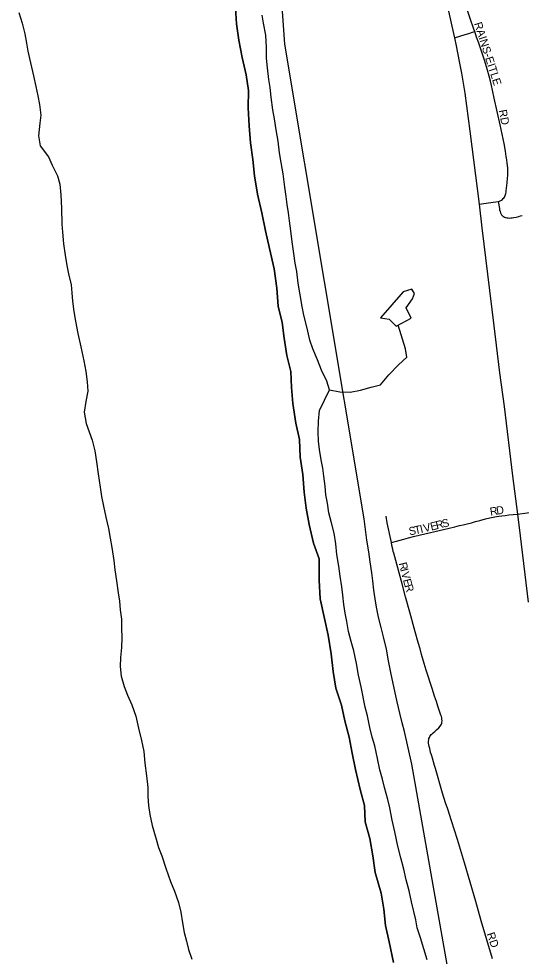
# Model space of a CAD drawing. Extents: x 1451455 to 1749751, y 218250 to 574981.
# Drawn here: x 1601926 to 1605068, y 245182 to 251036 of the extents above; entities that cross this region are included whole.
import ezdxf

# ---------------------------------------------------------------- set-up
doc = ezdxf.new("R2010")
doc.units = 0
for name, color, linetype in [('GM_X_City_Street', 7, 'Continuous'), ('GM_X_City_Street_Text', 7, 'Continuous'), ('GM_X_Corporation', 7, 'Continuous'), ('GM_X_County', 7, 'Continuous'), ('GM_X_Major_River', 7, 'Continuous'), ('GM_X_Minor_Lake', 7, 'Continuous'), ('GM_X_Minor_River', 7, 'Continuous'), ('GM_X_Township', 7, 'Continuous'), ('GM_X_US_Route', 7, 'Continuous')]:
    doc.layers.add(name, color=color, linetype=linetype)

msp = doc.modelspace()

# ---------------------------------------------------------------- linework, layer by layer
at = {"layer": 'GM_X_City_Street'}
for points in [[(1604776.7, 250957), (1604772.1, 250970.4), (1604749.1, 251038.3), (1604679.3, 251250.5), (1604645, 251349.6), (1604639.5, 251368.5), (1604636, 251382.3), (1604634.7, 251392.7), (1604634.3, 251401.8), (1604634.7, 251409.5), (1604635.5, 251416), (1604637.3, 251422.1)], [(1604650, 250917.2), (1604683.3, 250927), (1604717.2, 250937), (1604739.6, 250944.2), (1604762.7, 250952.2), (1604776.7, 250957)], [(1604923.9, 249895.9), (1604932.3, 249898.1), (1604939.2, 249900.7), (1604945.3, 249904.2), (1604950.9, 249908.5), (1604955.7, 249913.3), (1604959.2, 249916.8), (1604963.1, 249922.4), (1604965.7, 249926.7), (1604967.9, 249932.8), (1604969.4, 249938), (1604970.9, 249944.1), (1604972.7, 249952.4), (1604973.9, 249961.9), (1604978.8, 250011.1), (1604982.2, 250041.3), (1604983.3, 250056.8), (1604983.9, 250070.8), (1604983.9, 250079.9), (1604983.9, 250092.5), (1604983, 250105.1), (1604981.9, 250119), (1604980, 250135.1), (1604977.3, 250154.7), (1604974.3, 250175.8), (1604968.3, 250210.2), (1604960, 250257), (1604935.3, 250374.2), (1604917.1, 250457.1), (1604899.3, 250540.2), (1604888, 250591.2), (1604881.5, 250619.4), (1604875, 250647.2), (1604867.2, 250678.5), (1604857.2, 250714.9), (1604848.9, 250743.1), (1604840.7, 250770.9), (1604830.6, 250803.3), (1604819.9, 250834.3), (1604802.9, 250882.9), (1604789, 250922), (1604776.7, 250957)], [(1604803.8, 249878.4), (1604847.9, 249884.6), (1604891.4, 249890.7), (1604908.8, 249893.3), (1604923.9, 249895.9)], [(1604923.9, 249895.9), (1604930.9, 249851.2), (1604932.6, 249843), (1604935, 249831.8), (1604938.2, 249823.5), (1604941.7, 249816.5), (1604945.3, 249811.5), (1604949.1, 249806.9), (1604952.9, 249803.5), (1604957.7, 249800.5), (1604963.8, 249797.4), (1604970.3, 249794.8), (1604977.7, 249793.1), (1604985.6, 249792.3), (1604993.3, 249791.8), (1605002.1, 249792.1), (1605011.1, 249793.1), (1605021.7, 249794.5), (1605036.7, 249797.8), (1605053.6, 249802.2), (1605063.6, 249804.8), (1605073.6, 249808.3)], [(1605043.4, 247942.8), (1605103.7, 247950.2), (1605208.8, 247963.4)], [(1604255.8, 247765.2), (1604230.4, 247889), (1604223, 247929.2)], [(1604255.8, 247765.2), (1604286.8, 247773.6), (1604334.5, 247786.6), (1604363.6, 247794.4), (1604393.5, 247802.2), (1604437.4, 247813.3), (1604580.6, 247847.4), (1604617, 247856.1), (1604652.6, 247864.3), (1604682.1, 247870.8), (1604705, 247876.1), (1604730.3, 247882.5), (1604755.7, 247889.2), (1604781.5, 247896), (1604808.4, 247903.3), (1604844, 247912.5), (1604870.5, 247919), (1604891.7, 247923.9), (1604912.2, 247927.7), (1604927.4, 247930.2), (1604946.7, 247932.9), (1604966.6, 247935.1), (1604989.2, 247937.3), (1605043.4, 247942.8)], [(1604889, 245164.7), (1604817.3, 245403.4), (1604783.8, 245523.4), (1604712.8, 245765.8), (1604668.6, 245910.1), (1604631.9, 246027.5), (1604607.7, 246100.6), (1604595, 246140.7), (1604576.4, 246200.8), (1604531.6, 246354.3), (1604525.6, 246373.8), (1604519.1, 246395.9), (1604512.1, 246418.1), (1604506, 246438.5), (1604501.3, 246453.7), (1604497.3, 246468.9), (1604495.2, 246479.3), (1604492.1, 246492.3), (1604490, 246502.3), (1604488.7, 246512.3), (1604488.2, 246519.8), (1604488.2, 246525.8), (1604489.1, 246532.9), (1604490.8, 246540.5), (1604493.4, 246547.9), (1604496.8, 246554.2), (1604500.4, 246560.5), (1604505.2, 246566.1), (1604510.4, 246571.3), (1604517.8, 246577.8), (1604527.7, 246586.1), (1604538.9, 246595.3), (1604553.5, 246608.6), (1604561.7, 246618.7), (1604565.5, 246624.7), (1604568.1, 246630.1), (1604570.2, 246636), (1604571.8, 246642.6), (1604572.6, 246652.4), (1604571.6, 246662), (1604570.2, 246670.3), (1604568.4, 246678.2), (1604565.5, 246687.6), (1604559.4, 246706.3), (1604547.2, 246743.8), (1604537.3, 246772.7), (1604526.1, 246805.9), (1604510.8, 246853.4), (1604473.8, 246968.2), (1604461.8, 247009.3), (1604444.8, 247065.7), (1604434.8, 247100.8), (1604424, 247141.6), (1604405.2, 247207.8), (1604371.7, 247331.2), (1604344.9, 247425.9), (1604322.2, 247508.1), (1604270.9, 247698.1), (1604267.8, 247710.2), (1604264.3, 247724.5), (1604259.5, 247746.2), (1604255.8, 247765.2)]]:
    msp.add_lwpolyline(points, dxfattribs=at)
at = {"layer": 'GM_X_Corporation'}
msp.add_lwpolyline([(1604616.6, 245058.8), (1604383.4, 246381.5), (1604338.8, 246584.5), (1604323.4, 246638.8), (1604308.1, 246699.1), (1604292.9, 246771.4), (1604279.4, 246825.7), (1604252.8, 246954.3), (1604237.6, 247026.7), (1604224.4, 247099), (1604207.3, 247177.4), (1604191.9, 247235.7), (1604174.6, 247300), (1604163.3, 247362.3), (1604153.9, 247414.5), (1604146.4, 247468.7), (1604139.1, 247526.9), (1604133.6, 247577.1), (1604122.4, 247645.4), (1604115, 247707.6), (1604101.8, 247779.9), (1604094.6, 247846.1), (1604085, 247913.6), (1603589, 250877.2), (1603525.6, 251789.6)], dxfattribs=at)
at = {"layer": 'GM_X_County'}
msp.add_lwpolyline([(1603280.6, 251104.7), (1603286.5, 251005), (1603302.7, 250901.6), (1603322.8, 250794.6), (1603348.6, 250686.9), (1603362.2, 250589.3), (1603360.2, 250480), (1603366.2, 250366.8), (1603374.3, 250261.7), (1603390.3, 250157.3), (1603400.2, 250055.1), (1603418.4, 249941.5), (1603446.4, 249825), (1603468.4, 249711), (1603493.2, 249600.8), (1603522.2, 249475), (1603539.9, 249354.3), (1603547.9, 249241.3), (1603572, 249140.4), (1603585.9, 249041.1), (1603602, 248933.8), (1603627.7, 248832.7), (1603631.6, 248734.2), (1603639.7, 248633), (1603657.9, 248511.3), (1603681.6, 248408.3), (1603685.5, 248298.8), (1603701.6, 248190.1), (1603711.5, 248080.2), (1603723.6, 247979.2), (1603741.8, 247878), (1603768.1, 247762.1), (1603803.4, 247663.9), (1603805.3, 247530.6), (1603811.4, 247414.5), (1603837.7, 247290.7), (1603859.6, 247187), (1603879.4, 247069.7), (1603891.4, 246959.6), (1603907.7, 246855.2), (1603943.9, 246750.5), (1603965.7, 246651.1), (1603991.6, 246549.1), (1604011.5, 246449.4), (1604031.5, 246347), (1604059.6, 246224), (1604087.1, 246123.6), (1604091.2, 246021.2), (1604121.5, 245917.9), (1604139.2, 245809), (1604155.4, 245703.7), (1604191.4, 245575.2), (1604209.1, 245474.7), (1604219.2, 245374.2), (1604241.4, 245270.8), (1604269.6, 245143.6)], dxfattribs=at)
at = {"layer": 'GM_X_Major_River'}
for points in [[(1601925.9, 251076.2), (1601947.1, 251009.8), (1601964.4, 250941.5), (1601973.7, 250883.3), (1601983.2, 250833.1), (1602000.4, 250760.7), (1602017.5, 250680.4), (1602032.7, 250614.1), (1602046.1, 250555.8), (1602055.5, 250501.6), (1602064.7, 250433.3), (1602058.1, 250383.3), (1602049.3, 250305.2), (1602060.6, 250243), (1602111.8, 250174.2), (1602135.3, 250121.9), (1602168.5, 250055.4), (1602181.9, 250003.1), (1602189.2, 249936.9), (1602192.3, 249850.7), (1602195.2, 249754.4), (1602198.6, 249704.3), (1602205.8, 249630), (1602217, 249559.8), (1602226.3, 249495.5), (1602237.7, 249443.3), (1602253, 249375), (1602258.4, 249324.8), (1602261.8, 249272.6), (1602271.1, 249208.4), (1602280.5, 249148.2), (1602295.6, 249069.8), (1602314.7, 248987.4), (1602333.7, 248901), (1602345, 248832.8), (1602354.3, 248768.5), (1602357.6, 248710.4), (1602344.9, 248646.4), (1602334.2, 248580.3), (1602347.4, 248508), (1602366.8, 248455.7), (1602384.3, 248405.4), (1602401.6, 248339), (1602412.8, 248268.8), (1602422, 248194.5), (1602435.1, 248110.1), (1602444.4, 248051.9), (1602455.8, 247991.6), (1602471, 247923.3), (1602486.2, 247853), (1602497.6, 247792.7), (1602508.9, 247734.5), (1602520, 247652.2), (1602527.4, 247593.9), (1602536.7, 247525.7), (1602547.8, 247451.4), (1602555.3, 247399.2), (1602560.7, 247345), (1602568, 247286.8), (1602569.4, 247230.6), (1602570.8, 247170.5), (1602568.1, 247110.4), (1602561.4, 247048.3), (1602560.8, 246990.2), (1602566.1, 246930), (1602585.4, 246865.6), (1602606.9, 246811.2), (1602632.2, 246750.8), (1602657.4, 246680.4), (1602674.6, 246606), (1602693.8, 246529.6), (1602707.1, 246461.3), (1602714.3, 246387), (1602725.4, 246308.7), (1602732.6, 246236.5), (1602734, 246180.3), (1602737.4, 246122.2), (1602744.8, 246067.9), (1602760, 245997.6), (1602785.1, 245913.1), (1602800.6, 245860.8), (1602820, 245808.5), (1602845.2, 245732), (1602874.3, 245647.5), (1602899.6, 245587.1), (1602924.8, 245516.6), (1602940.2, 245456.3), (1602949.5, 245390), (1602960.8, 245329.8), (1602974.2, 245275.5), (1602987.7, 245223.2), (1603009, 245162.8)], [(1603627.2, 249712.2), (1603617.9, 249774.5), (1603612.4, 249824.6), (1603605, 249876.8), (1603597.5, 249927), (1603590.2, 249985.2), (1603579.1, 250067.5), (1603565.9, 250137.8), (1603556.6, 250200), (1603547.4, 250272.3), (1603536.2, 250342.6), (1603524.9, 250410.8), (1603515.6, 250467), (1603504.5, 250547.3), (1603497.1, 250607.5), (1603489.7, 250657.7), (1603480.5, 250730), (1603475.2, 250790.2), (1603475.9, 250856.3), (1603470.8, 250934.5), (1603455.6, 251008.8), (1603448.2, 251059)], [(1604479.5, 245158.3), (1604458.2, 245228.7), (1604436.9, 245297.1), (1604417.6, 245359.5), (1604408.2, 245409.7), (1604381.4, 245522.3), (1604366.1, 245590.6), (1604348.8, 245659), (1604333.6, 245725.3), (1604314.3, 245795.7), (1604295.1, 245870.1), (1604278.1, 245958.5), (1604260.9, 246030.9), (1604245.7, 246109.2), (1604234.3, 246161.5), (1604213.1, 246235.9), (1604199.6, 246288.1), (1604184.3, 246346.5), (1604169, 246416.8), (1604151.9, 246495.2), (1604136.5, 246549.5), (1604121.1, 246609.8), (1604105.9, 246682.1), (1604092.5, 246736.4), (1604065.9, 246865), (1604050.7, 246937.3), (1604037.5, 247009.6), (1604020.3, 247088), (1604004.9, 247146.3), (1603987.6, 247210.7), (1603976.3, 247272.9), (1603966.9, 247325.2), (1603959.5, 247379.4), (1603952.1, 247437.6), (1603946.7, 247487.8), (1603935.4, 247556), (1603928.1, 247618.3), (1603914.9, 247690.6), (1603907.6, 247756.8), (1603898.3, 247823.1), (1603881.1, 247889.4), (1603865.7, 247951.7), (1603856.4, 248012), (1603846.9, 248062.2), (1603841.5, 248116.4), (1603834.2, 248180.6), (1603826.8, 248230.8), (1603817.4, 248281), (1603806.1, 248345.3), (1603800.7, 248399.4), (1603797.3, 248457.6), (1603800, 248523.7), (1603806.8, 248589.8), (1603837.5, 248653.6), (1603868.2, 248719.4), (1603852.8, 248773.7), (1603819.6, 248842.2), (1603794.3, 248906.6), (1603765, 248975.1), (1603745.6, 249029.4), (1603728.4, 249103.8), (1603709.3, 249186.2), (1603697.9, 249238.4), (1603684.7, 249312.7), (1603673.5, 249385), (1603664.3, 249457.3), (1603654.9, 249509.5), (1603645.6, 249569.7), (1603636.4, 249644), (1603627.2, 249712.2)]]:
    msp.add_lwpolyline(points, dxfattribs=at)
at = {"layer": 'GM_X_Minor_Lake'}
for points in [[(1604379.5, 249166.2), (1604348.4, 249230.8), (1604387.2, 249286.4), (1604399.8, 249320.3), (1604384.1, 249346.6), (1604329.9, 249331.4), (1604187.3, 249169), (1604241.2, 249160.2), (1604286.6, 249117.4)], [(1604286.6, 249117.4), (1604379.5, 249166.2)]]:
    msp.add_lwpolyline(points, dxfattribs=at)
at = {"layer": 'GM_X_Minor_River'}
msp.add_lwpolyline([(1603868.2, 248719.4), (1603934.2, 248707.5), (1603998.2, 248704.5), (1604062.5, 248717.7), (1604128.8, 248734.8), (1604187.1, 248749.9), (1604240.1, 248813.4), (1604301, 248874.6), (1604351.8, 248922), (1604344.6, 248974.2), (1604298.2, 249123.5)], dxfattribs=at)
at = {"layer": 'GM_X_Township'}
msp.add_lwpolyline([(1604269.6, 245143.6), (1604241.4, 245270.8), (1604219.2, 245374.2), (1604209.1, 245474.7), (1604191.4, 245575.2), (1604155.4, 245703.7), (1604139.2, 245809), (1604121.5, 245917.9), (1604091.2, 246021.2), (1604087.1, 246123.6), (1604059.6, 246224), (1604031.5, 246347), (1604011.5, 246449.4), (1603991.6, 246549.1), (1603965.7, 246651.1), (1603943.9, 246750.5), (1603907.7, 246855.2), (1603891.4, 246959.6), (1603879.4, 247069.7), (1603859.6, 247187), (1603837.7, 247290.7), (1603811.4, 247414.5), (1603805.3, 247530.6), (1603803.4, 247663.9), (1603768.1, 247762.1), (1603741.8, 247878), (1603723.6, 247979.2), (1603711.5, 248080.2), (1603701.6, 248190.1), (1603685.5, 248298.8), (1603681.6, 248408.3), (1603657.9, 248511.3), (1603639.7, 248633), (1603631.6, 248734.2), (1603627.7, 248832.7), (1603602, 248933.8), (1603585.9, 249041.1), (1603572, 249140.4), (1603547.9, 249241.3), (1603539.9, 249354.3), (1603522.2, 249475), (1603493.2, 249600.8), (1603468.4, 249711), (1603446.4, 249825), (1603418.4, 249941.5), (1603400.2, 250055.1), (1603390.3, 250157.3), (1603374.3, 250261.7), (1603366.2, 250366.8), (1603360.2, 250480), (1603362.2, 250589.3), (1603348.6, 250686.9), (1603322.8, 250794.6), (1603302.7, 250901.6), (1603286.5, 251005), (1603280.6, 251104.7)], dxfattribs=at)
at = {"layer": 'GM_X_US_Route'}
msp.add_lwpolyline([(1604608.6, 251102.4), (1604634.4, 250990.2), (1604650, 250917.2), (1604660.8, 250867), (1604680.6, 250768.5), (1604694.3, 250697.5), (1604714.4, 250571), (1604746.9, 250333.7), (1604803.8, 249878.4), (1604822.2, 249731.4), (1604857.3, 249441.5), (1604897, 249119.1), (1604932.1, 248826), (1604960.6, 248614.7), (1605013.6, 248181.5), (1605043.4, 247942.8), (1605060.3, 247807.1), (1605111.4, 247393.7)], dxfattribs=at)

# ---------------------------------------------------------------- texts
at = {"layer": 'GM_X_City_Street_Text'}
for s, rotation, p in [('RAINS-EITLE', 287.81963, (1604772.2, 251006.7)), ('RD', 281.31414, (1604926.6, 250464.1)), ('R', 9.9095, (1604876, 247932.7)), ('D', 8.18226, (1604914.6, 247939.4)), ('V', 13.66611, (1604462.5, 247829.2)), ('E', 13.70836, (1604505.3, 247839.6)), ('R', 13.70638, (1604539.5, 247847.9)), ('S', 13.70817, (1604578, 247857.3)), ('S', 11.37155, (1604370, 247809.5)), ('T', 11.9384, (1604405, 247816.5)), ('I', 13.19041, (1604440.6, 247824.1)), ('R', 284.05613, (1604301.7, 247635.3)), ('I', 284.05523, (1604311.3, 247596.9)), ('V', 284.06275, (1604316.7, 247575.6)), ('E', 285.44901, (1604327.7, 247531.6)), ('R', 286.99122, (1604337.5, 247496.3)), ('RD', 288.43633, (1604851.5, 245321.6))]:
    msp.add_text(s, height=50, rotation=rotation, dxfattribs=at).set_placement(p)

doc.saveas('drawing.dxf')
